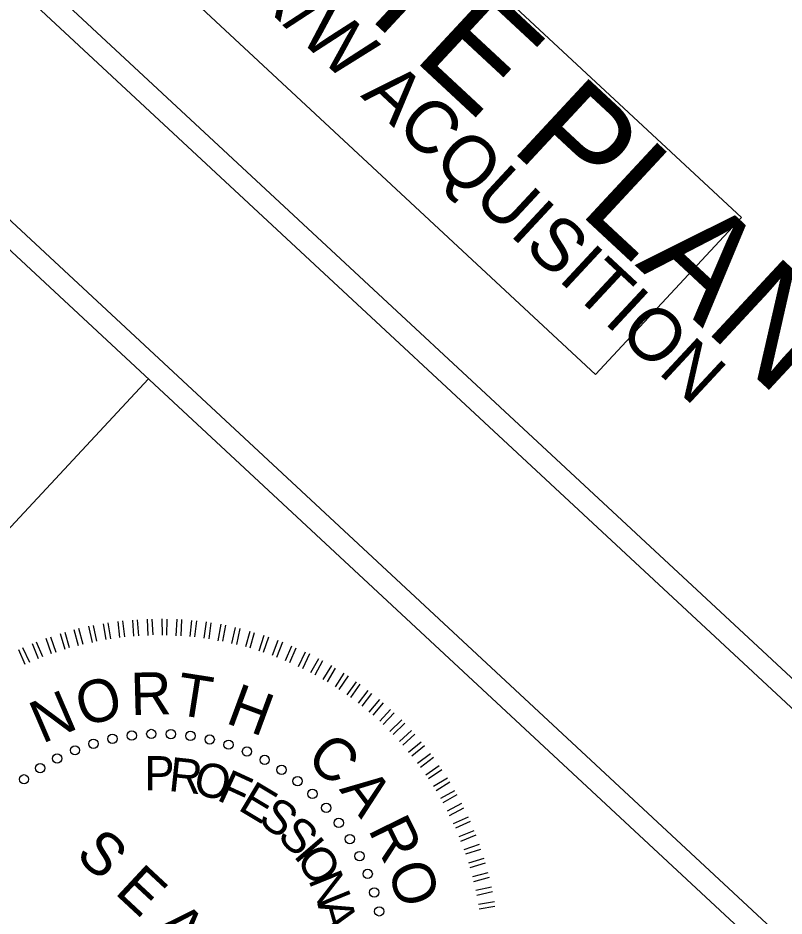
# Model space of a CAD drawing. Extents: x 2057696 to 2061410, y 685900 to 689434.
# Drawn here: x 2059188.9 to 2059259, y 688515.7 to 688597.9 of the extents above; entities that cross this region are included whole.
import ezdxf

# ---------------------------------------------------------------- set-up
doc = ezdxf.new("R2010")
doc.units = 0
for name, color, linetype in [('Default', 7, 'Continuous'), ('Exist Vertical Profile Vertical Axis Label', 7, 'Continuous'), ('Prop SS Fill Line', 7, 'Continuous')]:
    doc.layers.add(name, color=color, linetype=linetype)

msp = doc.modelspace()

# ---------------------------------------------------------------- linework, layer by layer
at = {"layer": 'Default'}
for p, q in [((2059279.198, 688516.629), (2058292.714, 689433.537)), ((2059279.015, 688519.53), (2058353.059, 689380.179)), ((2059256.982, 688512.703), (2058378.024, 689329.669)), ((2059200.863, 688564.864), (2058628.797, 687949.389))]:
    msp.add_line(p, q, dxfattribs=at)
for points in [[(2057696.329, 688791.897), (2058682.813, 687874.989), (2059279.198, 688516.629), (2058292.714, 689433.537)], [(2057714.84, 688796.536), (2058691.069, 687889.16), (2059265.668, 688507.36), (2058289.439, 689414.737)]]:
    msp.add_lwpolyline(points, close=True, dxfattribs=at)
at = {"layer": 'Exist Vertical Profile Vertical Axis Label'}
for p, q in [((2059196.16, 688540.886), (2059195.843, 688542.307)), ((2059197.004, 688541.023), (2059196.766, 688542.473)), ((2059197.426, 688541.091), (2059197.188, 688542.542)), ((2059198.245, 688541.201), (2059198.085, 688542.681)), ((2059198.72, 688541.271), (2059198.534, 688542.724)), ((2059199.541, 688541.328), (2059199.433, 688542.81)), ((2059199.99, 688541.371), (2059199.857, 688542.825)), ((2059200.838, 688541.402), (2059200.784, 688542.886)), ((2059201.288, 688541.445), (2059201.208, 688542.901)), ((2059202.138, 688541.423), (2059202.137, 688542.909)), ((2059202.562, 688541.438), (2059202.588, 688542.899)), ((2059203.414, 688541.363), (2059203.491, 688542.878)), ((2059203.865, 688541.353), (2059203.917, 688542.841)), ((2059204.69, 688541.304), (2059204.822, 688542.768)), ((2059205.116, 688541.266), (2059205.301, 688542.732)), ((2059205.969, 688541.138), (2059206.18, 688542.632)), ((2059206.423, 688541.075), (2059206.608, 688542.541)), ((2059207.251, 688540.92), (2059207.515, 688542.415)), ((2059207.677, 688540.882), (2059207.943, 688542.325)), ((2059193.243, 688540.116), (2059192.82, 688541.533)), ((2059193.636, 688540.263), (2059193.24, 688541.655)), ((2059194.478, 688540.453), (2059194.08, 688541.898)), ((2059194.898, 688540.574), (2059194.5, 688542.019)), ((2059195.74, 688540.764), (2059195.421, 688542.238)), ((2059208.507, 688540.674), (2059208.826, 688542.118)), ((2059208.935, 688540.583), (2059209.254, 688542.028)), ((2059209.765, 688540.375), (2059210.165, 688541.796)), ((2059210.168, 688540.257), (2059210.567, 688541.678)), ((2059190.806, 688539.257), (2059190.252, 688540.643)), ((2059191.225, 688539.432), (2059190.644, 688540.79)), ((2059192.01, 688539.726), (2059191.508, 688541.114)), ((2059192.43, 688539.847), (2059191.928, 688541.235)), ((2059211, 688539.995), (2059211.452, 688541.418)), ((2059211.402, 688539.877), (2059211.882, 688541.275)), ((2059212.209, 688539.588), (2059212.716, 688540.96)), ((2059212.613, 688539.417), (2059213.146, 688540.817)), ((2059189.605, 688538.735), (2059189.024, 688540.094)), ((2059190.023, 688538.91), (2059189.39, 688540.267)), ((2059213.394, 688539.101), (2059213.982, 688540.449)), ((2059213.799, 688538.93), (2059214.386, 688540.278)), ((2059214.582, 688538.56), (2059215.222, 688539.911)), ((2059214.986, 688538.389), (2059215.626, 688539.74)), ((2059215.716, 688538.018), (2059216.439, 688539.292)), ((2059216.122, 688537.794), (2059216.818, 688539.093)), ((2059216.854, 688537.37), (2059217.63, 688538.645)), ((2059217.233, 688537.171), (2059217.983, 688538.419)), ((2059217.967, 688536.694), (2059218.77, 688537.944)), ((2059218.32, 688536.468), (2059219.151, 688537.693)), ((2059219.028, 688535.963), (2059219.887, 688537.162)), ((2059219.382, 688535.737), (2059220.24, 688536.936)), ((2059220.065, 688535.205), (2059220.95, 688536.378)), ((2059220.42, 688534.926), (2059221.306, 688536.1)), ((2059221.05, 688534.392), (2059222.016, 688535.542)), ((2059221.405, 688534.113), (2059222.345, 688535.235)), ((2059222.009, 688533.551), (2059223.005, 688534.623)), ((2059222.339, 688533.245), (2059223.334, 688534.316)), ((2059222.945, 688532.63), (2059224.021, 688533.678)), ((2059223.247, 688532.349), (2059224.298, 688533.37)), ((2059223.828, 688531.707), (2059224.906, 688532.702)), ((2059224.132, 688531.373), (2059225.21, 688532.368)), ((2059224.66, 688530.729), (2059225.793, 688531.673)), ((2059224.964, 688530.395), (2059226.097, 688531.339)), ((2059225.466, 688529.724), (2059226.654, 688530.616)), ((2059225.744, 688529.362), (2059226.933, 688530.255)), ((2059226.221, 688528.663), (2059227.464, 688529.505)), ((2059226.472, 688528.328), (2059227.69, 688529.142)), ((2059226.923, 688527.601), (2059228.196, 688528.364)), ((2059227.176, 688527.212), (2059228.421, 688528.001)), ((2059227.6, 688526.511), (2059228.874, 688527.221)), ((2059227.8, 688526.121), (2059229.1, 688526.858)), ((2059228.226, 688525.367), (2059229.527, 688526.051)), ((2059228.4, 688524.948), (2059229.702, 688525.633)), ((2059228.773, 688524.193), (2059230.13, 688524.826)), ((2059228.973, 688523.802), (2059230.304, 688524.408)), ((2059229.267, 688523.016), (2059230.653, 688523.571)), ((2059229.441, 688522.598), (2059230.828, 688523.153)), ((2059229.735, 688521.813), (2059231.124, 688522.315)), ((2059229.883, 688521.42), (2059231.273, 688521.869)), ((2059230.151, 688520.607), (2059231.569, 688521.031)), ((2059230.273, 688520.187), (2059231.69, 688520.611)), ((2059230.516, 688519.347), (2059231.935, 688519.717)), ((2059230.612, 688518.899), (2059232.056, 688519.297)), ((2059230.8, 688518.11), (2059232.248, 688518.402)), ((2059230.896, 688517.663), (2059232.317, 688517.98)), ((2059231.033, 688516.819), (2059232.509, 688517.085)), ((2059231.101, 688516.396), (2059232.552, 688516.635))]:
    msp.add_line(p, q, dxfattribs=at)
for centre in [(2059199.342, 688532.246), (2059201.128, 688532.39), (2059202.92, 688532.377), (2059204.704, 688532.209), (2059195.841, 688531.495), (2059197.575, 688531.947), (2059206.467, 688531.885), (2059208.194, 688531.41), (2059194.153, 688530.894), (2059209.874, 688530.785), (2059192.523, 688530.148), (2059211.493, 688530.017), (2059190.965, 688529.262), (2059213.039, 688529.11), (2059189.49, 688528.245), (2059214.5, 688528.072), (2059215.864, 688526.91), (2059217.123, 688525.635), (2059218.265, 688524.254), (2059219.283, 688522.779), (2059220.168, 688521.221), (2059220.914, 688519.591), (2059221.515, 688517.903), (2059221.967, 688516.169)]:
    msp.add_circle(centre, 0.425, dxfattribs=at)
at = {"layer": 'Prop SS Fill Line'}
msp.add_lwpolyline([(2059158.347, 688642.786), (2059171.679, 688657.13), (2059255.084, 688579.608), (2059241.751, 688565.264)], close=True, dxfattribs=at)

# ---------------------------------------------------------------- texts
at = {"layer": 'Exist Vertical Profile Vertical Axis Label'}
for s, height, rotation, p in [('O', 3.883, 16.03622, (2059194.882, 688533.011)), ('R', 3.883, 1.50522, (2059199.274, 688534.1)), ('T', 3.883, 351.08367, (2059203.251, 688534.192)), ('H', 3.883, 339.70871, (2059207.817, 688533.431)), ('N', 3.883, 23.30172, (2059191.144, 688531.468)), ('C', 3.883, 317.9122, (2059215.135, 688529.956)), ('P', 3.115, 0.04746, (2059200.48, 688527.245)), ('R', 3.115, 353.86355, (2059202.631, 688527.191)), ('O', 3.115, 347.67964, (2059204.844, 688526.927)), ('F', 3.115, 335.31183, (2059207.012, 688526.396)), ('A', 3.883, 306.79562, (2059218.257, 688527.311)), ('E', 3.115, 329.12792, (2059208.955, 688525.511)), ('S', 3.115, 322.94401, (2059210.774, 688524.384)), ('S', 3.115, 316.7601, (2059212.527, 688522.909)), ('R', 3.883, 296.1157, (2059220.911, 688523.666)), ('S E A L', 3.8977, 317.09343, (2059194.082, 688521.211)), ('I', 3.115, 310.57619, (2059214.047, 688521.239)), ('O', 3.115, 304.39228, (2059214.271, 688520.929)), ('O', 3.883, 288.8502, (2059222.662, 688520.042)), ('N', 3.115, 292.02447, (2059215.454, 688519.062)), ('A', 3.115, 285.84056, (2059216.304, 688516.837))]:
    msp.add_text(s, height=height, rotation=rotation, dxfattribs=at).set_placement(p)
at = {"layer": 'Prop SS Fill Line'}
for s, height, p in [('INCOMPLETE PLANS', 9.6, (2059170.063, 688645.207)), ('DO NOT USE FOR R/W ACQUISITION', 4.8, (2059167.964, 688639.251))]:
    msp.add_text(s, height=height, rotation=317.09343, dxfattribs=at).set_placement(p)

doc.saveas('drawing.dxf')
